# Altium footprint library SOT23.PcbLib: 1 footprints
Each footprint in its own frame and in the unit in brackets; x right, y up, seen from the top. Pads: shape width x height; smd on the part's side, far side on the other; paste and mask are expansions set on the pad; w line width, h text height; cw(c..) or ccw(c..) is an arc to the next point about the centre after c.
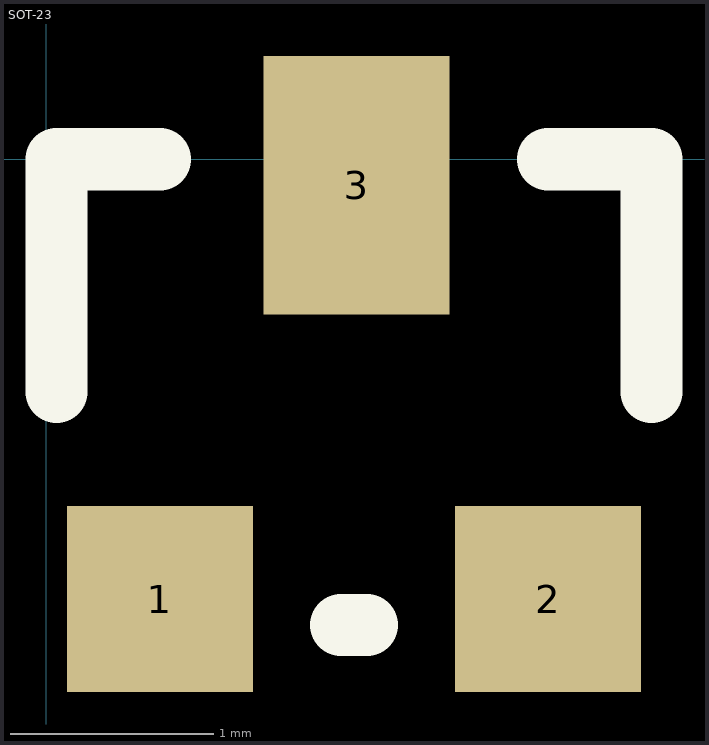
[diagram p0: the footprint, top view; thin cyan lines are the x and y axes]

## SOT-23 [mil]
pads (3):
  rect 36x36 smd: 1(22,-85) 2(97,-85)
  rect 36x50 smd: 3(60,-5)
Top Overlay:
  lines w12: 2,-45 2,0 22,0 ; 57,-90 62,-90 ; 97,0 117,0 117,-45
